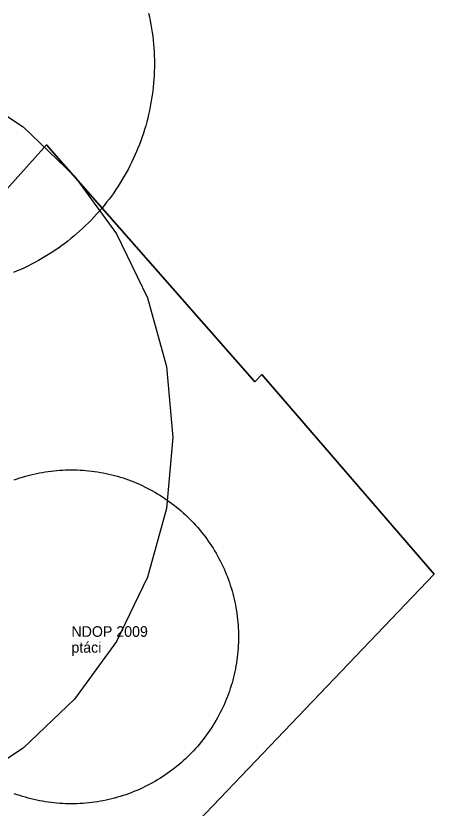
# Model space of a CAD drawing. Extents: x -477403 to -465463, y -1159182 to -1149227.
# Drawn here: x -471399.6 to -471320.7, y -1155140.9 to -1154991.4 of the extents above; entities that cross this region are included whole.
import ezdxf

# ---------------------------------------------------------------- set-up
doc = ezdxf.new("R2010")
doc.units = 0
for name, color, linetype in [('Vrstva 1', 7, 'Continuous'), ('Vrstva 10_stav', 7, 'Continuous'), ('Vrstva 2', 7, 'Continuous')]:
    doc.layers.add(name, color=color, linetype=linetype)

msp = doc.modelspace()

# ---------------------------------------------------------------- linework, layer by layer
at = {"layer": 'Vrstva 10_stav'}
for points in [[(-471374.57, -1154990.898), (-471374.409, -1154991.622), (-471374.261, -1154992.348), (-471374.126, -1154993.077), (-471374.004, -1154993.809), (-471373.894, -1154994.542), (-471373.798, -1154995.277), (-471373.714, -1154996.013), (-471373.643, -1154996.751), (-471373.584, -1154997.49), (-471373.539, -1154998.23), (-471373.507, -1154998.971), (-471373.487, -1154999.712), (-471373.481, -1155000.453)], [(-471373.481, -1155000.453), (-471373.487, -1155001.194), (-471373.507, -1155001.935), (-471373.539, -1155002.676), (-471373.584, -1155003.416), (-471373.643, -1155004.155), (-471373.714, -1155004.893), (-471373.798, -1155005.629), (-471373.894, -1155006.364), (-471374.004, -1155007.098), (-471374.126, -1155007.829), (-471374.261, -1155008.558), (-471374.409, -1155009.284), (-471374.57, -1155010.008), (-471374.743, -1155010.729), (-471374.928, -1155011.446), (-471375.126, -1155012.161), (-471375.337, -1155012.872), (-471375.56, -1155013.579), (-471375.795, -1155014.282), (-471376.042, -1155014.98), (-471376.302, -1155015.675), (-471376.574, -1155016.364), (-471376.857, -1155017.049), (-471377.153, -1155017.729), (-471377.46, -1155018.404), (-471377.78, -1155019.073), (-471378.11, -1155019.736), (-471378.453, -1155020.394), (-471378.806, -1155021.045), (-471379.171, -1155021.69), (-471379.548, -1155022.329), (-471379.935, -1155022.961), (-471380.333, -1155023.587), (-471380.743, -1155024.205), (-471381.162, -1155024.816), (-471381.593, -1155025.419), (-471382.034, -1155026.015), (-471382.485, -1155026.603), (-471382.947, -1155027.183), (-471383.418, -1155027.755), (-471383.9, -1155028.319), (-471384.391, -1155028.874), (-471384.892, -1155029.421), (-471385.402, -1155029.959), (-471385.922, -1155030.487), (-471386.45, -1155031.007), (-471386.988, -1155031.517), (-471387.535, -1155032.018), (-471388.09, -1155032.509), (-471388.653, -1155032.991), (-471389.225, -1155033.462), (-471389.806, -1155033.924), (-471390.394, -1155034.375), (-471390.99, -1155034.816), (-471391.593, -1155035.246), (-471392.204, -1155035.666), (-471392.822, -1155036.075), (-471393.448, -1155036.474), (-471394.08, -1155036.861), (-471394.718, -1155037.237), (-471395.364, -1155037.602), (-471396.015, -1155037.956), (-471396.673, -1155038.298), (-471397.336, -1155038.629), (-471398.005, -1155038.948), (-471398.68, -1155039.256), (-471399.36, -1155039.551), (-471400.044, -1155039.835)], [(-471409.46, -1155004.955), (-471398.238, -1155012.363), (-471388.52, -1155021.655), (-471380.616, -1155032.533), (-471374.782, -1155044.647), (-471371.205, -1155057.608), (-471370, -1155071), (-471371.205, -1155084.392), (-471374.782, -1155097.353), (-471380.616, -1155109.467), (-471388.52, -1155120.345), (-471398.238, -1155129.637), (-471409.46, -1155137.045)], [(-471371.906, -1155150.375), (-471320.719, -1155096.75), (-471353.219, -1155059.125), (-471354.531, -1155060.5), (-471393.844, -1155015.75), (-471432.531, -1155059), (-471440.406, -1155052.375), (-471468.969, -1155084), (-471485, -1155098.125), (-471485.5, -1155098.625), (-471486.75, -1155112.75), (-471511.656, -1155134.625), (-471491.062, -1155162.875), (-471477.031, -1155181.5), (-471493.156, -1155192.625), (-471493.656, -1155192.875), (-471506.594, -1155199.125), (-471525.406, -1155208), (-471523.906, -1155216.5), (-471524.656, -1155223.625), (-471528.719, -1155228.875)], [(-471432.531, -1155059), (-471393.844, -1155015.75), (-471354.531, -1155060.5), (-471353.219, -1155059.125), (-471320.719, -1155096.75), (-471371.906, -1155150.375)], [(-471399.908, -1155078.985), (-471399.389, -1155078.802), (-471398.868, -1155078.627), (-471398.343, -1155078.462), (-471397.816, -1155078.306), (-471397.286, -1155078.159), (-471396.754, -1155078.021), (-471396.219, -1155077.893), (-471395.682, -1155077.774), (-471395.143, -1155077.664), (-471394.603, -1155077.564), (-471394.06, -1155077.473), (-471393.516, -1155077.392), (-471392.971, -1155077.32), (-471392.425, -1155077.258), (-471391.877, -1155077.205), (-471391.329, -1155077.162), (-471390.78, -1155077.128), (-471390.231, -1155077.104), (-471389.681, -1155077.09), (-471389.131, -1155077.085), (-471388.581, -1155077.09), (-471388.032, -1155077.104), (-471387.482, -1155077.128), (-471386.933, -1155077.162), (-471386.385, -1155077.205), (-471385.838, -1155077.258), (-471385.291, -1155077.32), (-471384.746, -1155077.392), (-471384.202, -1155077.473), (-471383.66, -1155077.564), (-471383.119, -1155077.664), (-471382.58, -1155077.774), (-471382.043, -1155077.893), (-471381.509, -1155078.021), (-471380.976, -1155078.159), (-471380.446, -1155078.306), (-471379.919, -1155078.462), (-471379.394, -1155078.627), (-471378.873, -1155078.802), (-471378.355, -1155078.985), (-471377.839, -1155079.178), (-471377.328, -1155079.379), (-471376.82, -1155079.59), (-471376.316, -1155079.809), (-471375.815, -1155080.037), (-471375.319, -1155080.274), (-471374.827, -1155080.519), (-471374.339, -1155080.773), (-471373.856, -1155081.036), (-471373.377, -1155081.306)], [(-471373.377, -1155081.306), (-471372.903, -1155081.586), (-471372.434, -1155081.873), (-471371.97, -1155082.168), (-471371.512, -1155082.472), (-471371.059, -1155082.783), (-471370.611, -1155083.103), (-471370.169, -1155083.43), (-471369.733, -1155083.765), (-471369.302, -1155084.107), (-471368.878, -1155084.457), (-471368.46, -1155084.814), (-471368.048, -1155085.178), (-471367.642, -1155085.55), (-471367.244, -1155085.928), (-471366.851, -1155086.314), (-471366.466, -1155086.706), (-471366.087, -1155087.105), (-471365.716, -1155087.51), (-471365.352, -1155087.922), (-471364.994, -1155088.34), (-471364.645, -1155088.765), (-471364.302, -1155089.195), (-471363.967, -1155089.631), (-471363.64, -1155090.073), (-471363.321, -1155090.521), (-471363.01, -1155090.974), (-471362.706, -1155091.433), (-471362.41, -1155091.897), (-471362.123, -1155092.366), (-471361.844, -1155092.839), (-471361.573, -1155093.318), (-471361.311, -1155093.801), (-471361.057, -1155094.289), (-471360.811, -1155094.781), (-471360.575, -1155095.277), (-471360.347, -1155095.778), (-471360.127, -1155096.282), (-471359.917, -1155096.79), (-471359.715, -1155097.302), (-471359.523, -1155097.817), (-471359.339, -1155098.336), (-471359.165, -1155098.857), (-471359, -1155099.381), (-471358.843, -1155099.909), (-471358.696, -1155100.439), (-471358.559, -1155100.971), (-471358.43, -1155101.506), (-471358.311, -1155102.043), (-471358.202, -1155102.582), (-471358.101, -1155103.122), (-471358.011, -1155103.665), (-471357.929, -1155104.209), (-471357.858, -1155104.754), (-471357.795, -1155105.3), (-471357.743, -1155105.848), (-471357.7, -1155106.396), (-471357.666, -1155106.945), (-471357.642, -1155107.494), (-471357.627, -1155108.044), (-471357.623, -1155108.594)], [(-471357.623, -1155108.594), (-471357.627, -1155109.143), (-471357.642, -1155109.693), (-471357.666, -1155110.243), (-471357.7, -1155110.792), (-471357.743, -1155111.34), (-471357.795, -1155111.887), (-471357.858, -1155112.434), (-471357.929, -1155112.979), (-471358.011, -1155113.523), (-471358.101, -1155114.065), (-471358.202, -1155114.606), (-471358.311, -1155115.145), (-471358.43, -1155115.681), (-471358.559, -1155116.216), (-471358.696, -1155116.749), (-471358.843, -1155117.279), (-471359, -1155117.806), (-471359.165, -1155118.33), (-471359.339, -1155118.852), (-471359.523, -1155119.37), (-471359.715, -1155119.885), (-471359.917, -1155120.397), (-471360.127, -1155120.905), (-471360.347, -1155121.409), (-471360.575, -1155121.91), (-471360.811, -1155122.406), (-471361.057, -1155122.898), (-471361.311, -1155123.386), (-471361.573, -1155123.869), (-471361.844, -1155124.348), (-471362.123, -1155124.822), (-471362.41, -1155125.291), (-471362.706, -1155125.754), (-471363.01, -1155126.213), (-471363.321, -1155126.666), (-471363.64, -1155127.114), (-471363.967, -1155127.556), (-471364.302, -1155127.992), (-471364.645, -1155128.423), (-471364.994, -1155128.847), (-471365.352, -1155129.265), (-471365.716, -1155129.677), (-471366.087, -1155130.082), (-471366.466, -1155130.481), (-471366.851, -1155130.873), (-471367.244, -1155131.259), (-471367.642, -1155131.637), (-471368.048, -1155132.009), (-471368.46, -1155132.373), (-471368.878, -1155132.73), (-471369.302, -1155133.08), (-471369.733, -1155133.423), (-471370.169, -1155133.757), (-471370.611, -1155134.085), (-471371.059, -1155134.404), (-471371.512, -1155134.715), (-471371.97, -1155135.019), (-471372.434, -1155135.314), (-471372.903, -1155135.602), (-471373.377, -1155135.881), (-471373.856, -1155136.152), (-471374.339, -1155136.414), (-471374.827, -1155136.668), (-471375.319, -1155136.913), (-471375.815, -1155137.15), (-471376.316, -1155137.378), (-471376.82, -1155137.597), (-471377.328, -1155137.808), (-471377.839, -1155138.009), (-471378.355, -1155138.202), (-471378.873, -1155138.385), (-471379.394, -1155138.56), (-471379.919, -1155138.725), (-471380.446, -1155138.882), (-471380.976, -1155139.028), (-471381.509, -1155139.166), (-471382.043, -1155139.294), (-471382.58, -1155139.413), (-471383.119, -1155139.523), (-471383.66, -1155139.623), (-471384.202, -1155139.714), (-471384.746, -1155139.796), (-471385.291, -1155139.867), (-471385.838, -1155139.929), (-471386.385, -1155139.982), (-471386.933, -1155140.025), (-471387.482, -1155140.059), (-471388.032, -1155140.083), (-471388.581, -1155140.097), (-471389.131, -1155140.102), (-471389.681, -1155140.097), (-471390.231, -1155140.083), (-471390.78, -1155140.059), (-471391.329, -1155140.025), (-471391.877, -1155139.982), (-471392.425, -1155139.929), (-471392.971, -1155139.867), (-471393.516, -1155139.796), (-471394.06, -1155139.714), (-471394.603, -1155139.623)], [(-471394.603, -1155139.623), (-471395.143, -1155139.523), (-471395.682, -1155139.413), (-471396.219, -1155139.294), (-471396.754, -1155139.166), (-471397.286, -1155139.028), (-471397.816, -1155138.882), (-471398.343, -1155138.725), (-471398.868, -1155138.56), (-471399.389, -1155138.385), (-471399.908, -1155138.202)]]:
    msp.add_lwpolyline(points, dxfattribs=at)

# ---------------------------------------------------------------- texts
at = {"layer": 'Vrstva 1'}
msp.add_text('ptáci', height=2, dxfattribs=at).set_placement((-471389.131, -1155111.593))
msp.add_text('ptáci', height=2, dxfattribs=at).set_placement((-471389.131, -1155111.593))
at = {"layer": 'Vrstva 2'}
msp.add_text('NDOP 2009', height=2, dxfattribs=at).set_placement((-471389.131, -1155108.593))
msp.add_text('NDOP 2009', height=2, dxfattribs=at).set_placement((-471389.131, -1155108.593))

doc.saveas('drawing.dxf')
